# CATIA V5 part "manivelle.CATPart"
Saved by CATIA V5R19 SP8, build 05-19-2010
Part number: manivelle
Bounding box of the stored display mesh (mm): x 0 to 70, y 0 to 20, z -21 to 20
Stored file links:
  C:\Users\rcousturie\Desktop\EU_thinkMotion\iao\IAO_MMS_Groupe1\abaussand\abaussand\Modélisation\manivelle.CATPart
  C:\Users\rcousturie\Desktop\EU_thinkMotion\iao\IAO_MMS_Groupe1\abaussand\abaussand\Modélisation\abaussand.CATProduct
  C:\Users\rcousturie\Desktop\EU_thinkMotion\iao\IAO_MMS_Groupe1\abaussand\abaussand\Modélisation\bati.CATPart
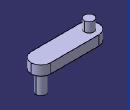
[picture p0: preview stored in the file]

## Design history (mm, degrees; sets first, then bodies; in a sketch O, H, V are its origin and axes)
Parameters
  entraxe = 50 mm
Set1
  DatumSurface1: linked copy from another document
Body1 (main body)
  Sketch1 on yz-plane, origin (0, 0, 0), H (0, 1, 0), V (0, 0, 1)
    line L1 (0, 10) -> (20, 10)
    line L2 (20, 10) -> (20, 0)
    line L3 (20, 0) -> (0, 0)
    line L4 (0, 0) -> (0, 10)
    point P3 (20, 0)
    point P4 (0, 0)
    length L1 = 20
    length L2 = 10
    horizontal: L1 H, L3 H
    vertical: L2 V, L4 V
    coincidence: P3 H, P4 O
  Pad1: profile Sketch1, direction (1, 0, 0), length 70 {= entraxe + 20mm}
  Sketch2 on face of Pad1 from Sketch1.L1, origin (0, 0, 10), H (1, 0, 0), V (0, 1, 0)
    circle A1 centre (10, 10) radius 5
    point P1 (10, 10)
    reference projected line E1 (0, 20) -> (0, 0) from edge [start face of Pad1 | face of Pad1 from Sketch1.L1]
    reference projected line E2 (0, 20) -> (120, 20) from edge [face of Pad1 from Sketch1.L1 | face of Pad1 from Sketch1.L2]
    distance P1 E1 = 10
    radius A1 = 5
    distance P1 E2 = 10
  Pad2: profile Sketch2, direction (0, 0, 1), up to face of DatumSurface1
  Sketch3 on face of Pad1 from Sketch1.L3, origin (0, 0, 0), H (1, 0, 0), V (0, -1, 0)
    circle A1 centre (60, -10) radius 5
    point P1 (60, -10)
    reference projected line E1 (0, -20) -> (120, -20) from edge [face of Pad1 from Sketch1.L2 | face of Pad1 from Sketch1.L3]
    reference projected line E2 (0, 0) -> (0, -20) from edge [start face of Pad1 | face of Pad1 from Sketch1.L3]
    radius A1 = 5
    distance P1 E1 = 10
    distance P1 E2 = 60 {= entraxe + 10mm}
  Pad3: profile Sketch3, direction (0, 0, -1), length 21
  Fillet1: radius 10, on edge [start face of Pad1 | face of Pad1 from Sketch1.L4]; edge [start face of Pad1 | face of Pad1 from Sketch1.L2]; edge [face of Pad1 from Sketch1.L4 | end face of Pad1]; edge [face of Pad1 from Sketch1.L2 | end face of Pad1]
